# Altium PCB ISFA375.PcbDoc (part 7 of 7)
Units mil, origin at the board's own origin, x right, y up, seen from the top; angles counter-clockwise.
Board outline 5615 x 5520 mil, 6 copper layers (Top_SL, GND, POWER, Signal_Layer, GND2, Bottom_SL), stack 60.472 mil thick; 494 components, 307 nets, 1648 pads, 755 vias.
Unrouted connection lines stored in the file: 315.
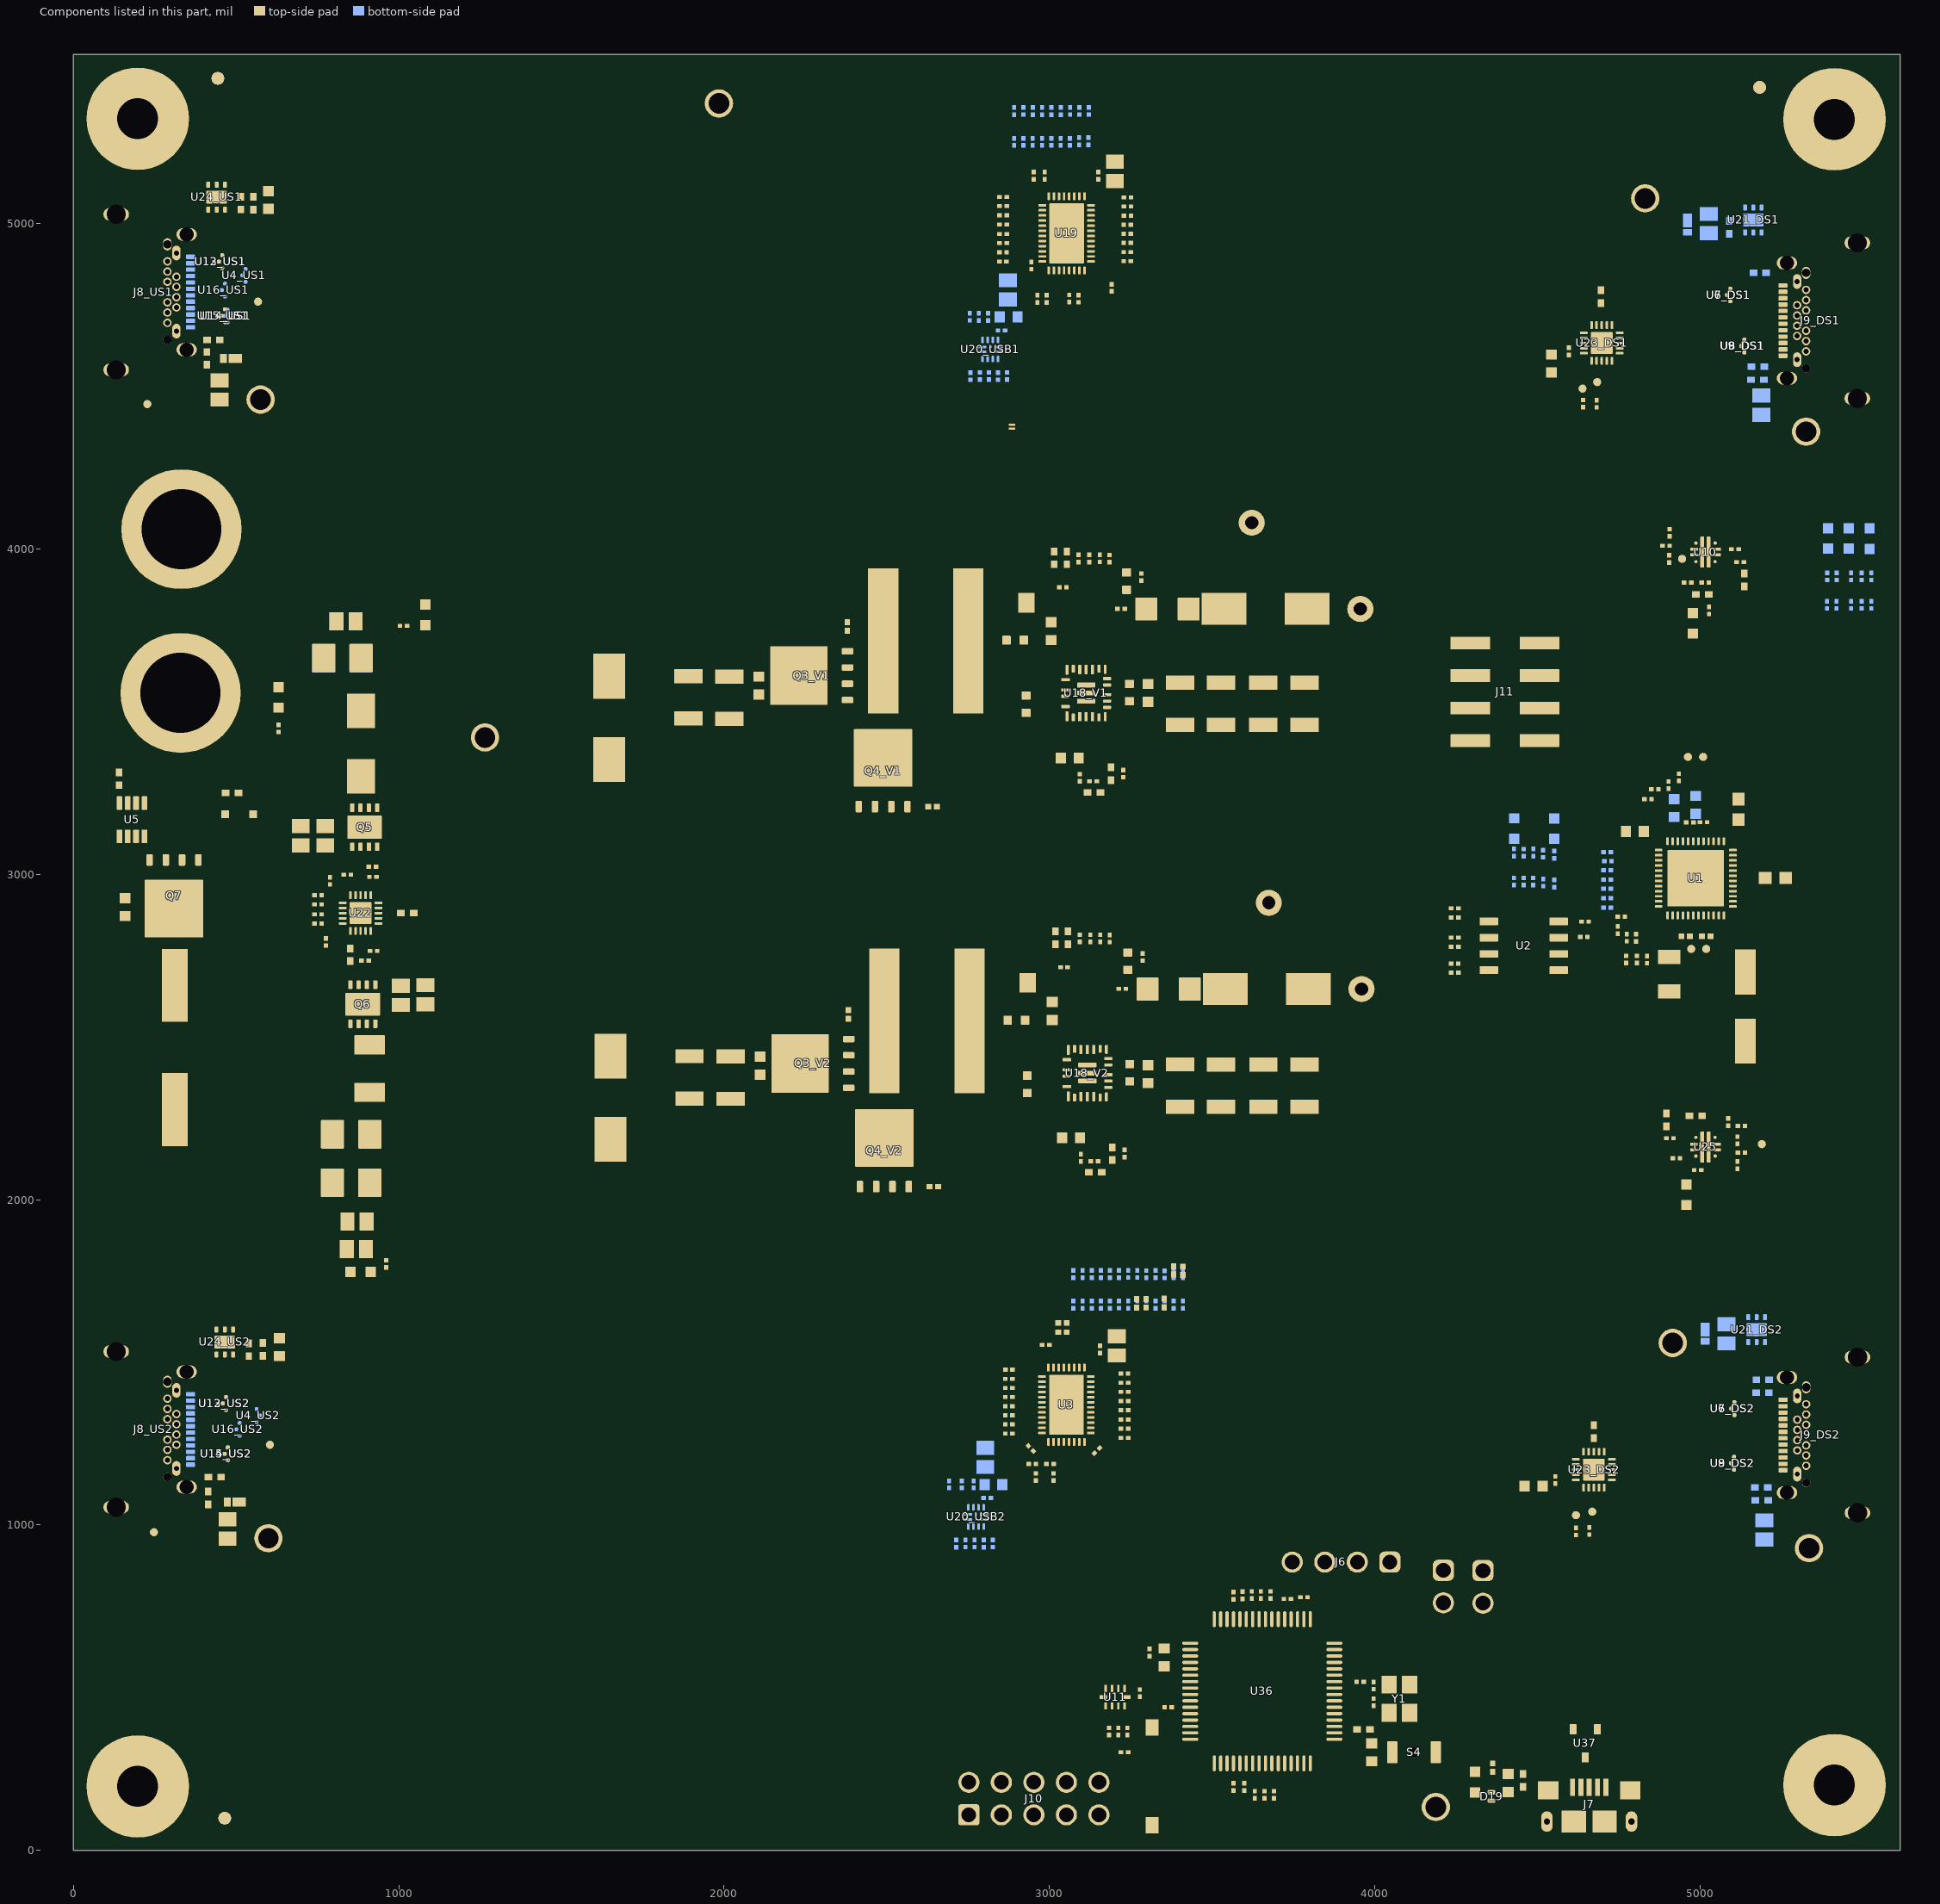
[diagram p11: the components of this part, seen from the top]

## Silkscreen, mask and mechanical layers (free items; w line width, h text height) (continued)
M10 Fab Notes:
  drawing of 189 lines, arcs and shapes, not listed
  text "DESIGN INFORMATION" at 12053.02,6356.17 h30
  text "MIN. TRACK WIDTH:" at 11408.46,6224.05 h30
  text "4.32" at 12504.7,6224.05 h30
  text "MIL" at 12659.46,6224.05 h30
  text "4mil" at 12474.71,6118 h30
  text "MIN. CLEARANCE:" at 11408.46,6099.92 h30
  text "MIL" at 12659.46,6099.92 h30
  text "MIN. VIA PAD SIZE:" at 11408.46,5975.8 h30
  text "4" at 12474.71,5975.8 h30
  text "MIL" at 12659.46,5975.8 h30
  text "0.1mm (4MIL)" at 12103.46,5845.9 h30
  text "MINIMUM ANNULAR RING" at 11079.23,5837.68 h30
  text "EXTERNAL" at 12811.46,5837.68 h30
  text "PER" at 11279.23,5727.55 h30
  text "IPC-D-275 CLASS 2 LEVEL C" at 11499.23,5727.54 h30
  text "MIL, HOLES" at 12987.46,5627.07 h30
  text "+/-" at 12595,5618.48 h30
  text "+/-" at 13449,5618.48 h30
  text "REGISTRATION TOLERANCES:" at 11079.23,5617.42 h30
  text "METAL" at 12279,5617.42 h30
  text "5" at 12855.2,5617.42 h30
  text "3" at 13688.2,5617.42 h30
  text "MIL" at 13804.46,5617.42 h30
  text "HOLE SIZE TOLERANCE (UNLESS OTHERWISE SPECIFIED):" at 11079.23,5519.1 h30
  text "+/-" at 13449,5516.23 h30
  text "3" at 13688.2,5515.17 h30
  text "MIL" at 13804.46,5515.17 h30
  text "MATERIAL:" at 11004.46,5377.52 h30
  text "FR-4 High Tg" at 11990.9,5249 h30
  text "X" at 11846.46,5241.01 h30
  text "FR-408" at 11425.46,5236.49 h30
  text "OTHER" at 12913.46,5236.49 h30
  text "62 MIL (1.6mm) +/-10%" at 11745.56,5093.46 h30
  text "X" at 11625.46,5091.01 h30
  text "THICKNESS:" at 11079.23,5085.24 h30
  text "OTHER" at 13030.46,5085.24 h30
  text "TOLERANCE:" at 11079.23,4946.92 h30
  text "X" at 11927.46,4946.92 h30
  text "ANSI IPC-6012 TYPE 3 CLASS 2" at 12105.48,4946.92 h30
  text "OTHER +/-" at 12105.46,4802.73 h30
  text "BOW & TWIST:" at 11079.23,4657.54 h30
  text "X" at 11927.46,4657.54 h30
  text "ANSI IPC-6012 TYPE 3 CLASS 2" at 12105.48,4657.54 h30
  text "OTHER +/-" at 12105.46,4510.85 h30
  text "DRILLING:" at 11004.46,4380.23 h30
  text "NC_DRILL FILES" at 12765.46,4275.04 h30
  text "REFERENCE:" at 11079.23,4271.1 h30
  text "X" at 11736.46,4271.01 h30
  text "AS SHOWN" at 11914.46,4271.1 h30
  text "X" at 12637.46,4271.1 h30
  text "OTHER" at 13063.46,4128.85 h30
  text "PTH COPPER THICKNESS:" at 11078.91,4125.32 h30
  text "X" at 12218.14,4125.32 h30
  text "20-30 um" at 12346.14,4125.32 h30
  text "BOARD FINISH:" at 11004.46,3977.73 h30
  text "SILKSCREEN:" at 11159.68,3867.6 h30
  text "X" at 12117.46,3867.6 h30
  text "TOP" at 12234.46,3867.6 h30
  text "X" at 12627.46,3867.6 h30
  text "BOTTOM" at 12745.46,3867.6 h30
  text "SILKSCREEN COLOR:" at 11159.68,3712.41 h30
  text "X" at 12116.46,3712.41 h30
  text "WHITE" at 12234.46,3712.41 h30
  text "OTHER" at 12745.46,3712.41 h30
  text "X" at 12247.46,3568.96 h30
  text "GREEN" at 12365.46,3568.96 h30
  text "OTHER" at 12983.46,3568.96 h30
  text "SOLDER RESIST COLOR:" at 11159.68,3562.1 h30
  text "X" at 12247.46,3414.71 h30
  text "MATTE" at 12365.46,3414.71 h30
  text "SEMI-GLOSS" at 12983,3414.07 h30
  text "IMMERSION GOLD (ENIG)" at 12065.46,3241.94 h30
  text "ENEPIG" at 13403,3234.72 h30
  text "SURFACE FINISH:" at 11004.46,3233.72 h30
  text "X" at 11887.46,3233.72 h30
  text "IMM. TIN/SILVER OR EQUIV" at 11334,3096.4 h30
  text "OTHER" at 12765.46,3092.47 h30
  text "ARRAY/PANEL:" at 11004.46,2937.09 h30
  text "CUT AND TRIM PER M1 BOARD OUTLINE" at 12065.46,2928.87 h30
  text "N.C. ROUTE" at 12065.46,2792.9 h30
  text "X" at 12753.46,2792.9 h30
  text "V. SCORE" at 12931.46,2792.9 h30
  text "CERTIFICATION:" at 11004.46,2663.77 h30
  text "MATERIALS AND WORKMANSHIP FOR ALL PCBS" at 11729.46,2663.77 h30
  text "TO MEET OR EXCEED THE REQUIREMENTS OF:" at 11729.46,2569.71 h30
  text "X" at 11366.97,2441.08 h30
  text "ANSI IPC-A-600F CLASS ->" at 11494.96,2441.08 h30
  text "X" at 13142.97,2441.08 h30
  text "2" at 13252.96,2441.08 h30
  text "1" at 12937.96,2439.58 h30
  text "3" at 13606.96,2439.58 h30
  text "X" at 12178.97,2293.39 h30
  text "RoHS" at 12306.96,2293.39 h30
  text "OTHER" at 12951.36,2293.39 h30
  text "PER ORDER" at 13348.42,2293.39 h30
  text "ALL BOARDS MUST MEET OR EXCEED UL94-V0 REQUIREMENTS." at 11032,2139.57 h30
  text "PCB MUST BEAR THE UL94V-0 UL REGISTERED MATERIAL ID NUMBER" at 11032,2023.5 h30
  text "ADDITIONAL REQUIREMENTS:" at 11004.46,1854.08 h30
  text "MICROSECTION:" at 11079.23,1746.95 h30
  text "YES" at 11984.96,1746.95 h30
  text "REQUIRED" at 12846.46,1602.62 h30
  text "BARE BOARD ELEC. TEST:" at 11079.23,1599.76 h30
  text "NONE" at 12384.96,1599.76 h30
  text "X" at 12728.46,1599.76 h30
  text "PER ORDER" at 13438.46,1599.76 h30
  text "XX MIL VIAS REQUIRE NON-CONDUCTIVE FILL AND PLANARIZE" at 10683,1394 h30
  text "XX MIL VIAS REQUIRE CONDUCTIVE FILL AND PLANARIZE" at 11255.38,1290.84 h30
  text "X" at 11141.97,1139.39 h30
  text "LAYER 4 (INNER LAYER) 4.32 MIL WIDE,  / TRACES REQUIRE 90 OHM DIFFERENTIAL IMPEDANCE" at 11246.39,1116.41 h30
  text "X" at 11149.97,973.39 h30
  text "LAYER 1 & 6 (OUTER LAYERS) 6.5 MIL WIDE,  / TRACES REQUIRE 90 OHM DIFFERENTIAL IMPEDANCE" at 10624,898 h30
  text ".Layer_Name" at 248,-858.49 h30
M11 Gerber Information:
  lines w10: -621,-930.17 5979,-930.17 ; -621,-726.83 5981,-726.83 ; -621,-523.5 -621,-1133.5 3384,-1133.5 5981,-1133.5 5981,-523.5 -620.5,-523.5 -620.5,-1133.5 955,-1133.5 ; 1844,-1133.5 1844,-523.5 ; 3111,-726.83 3111,-523.5 ; 3951,-726.83 3951,-523.5 ; 4573,-1140 4573,-937.17
  text "ALL ARTWORK VIEWED FROM TOP SIDE" at -557.5,-655.67 h30
  text "BOARD #:" at 1919,-655.67 h30
  text ".PRJ_Number" at 2464.5,-655.67 h30
  text "REV:" at 3309,-655.67 h30
  text ".PCB_Rev" at 3600.5,-655.67 h30
  text "SVN REV:" at 4147,-655.67 h30
  text ".VersionControl_RevNumber" at 4653,-655.67 h30
  text "LAYER NAME =" at -557.5,-858.49 h30
  text "TID #:" at 1919,-859 h30
  text ".TID" at 2464.5,-859 h30
  text "PLOT NAME =" at -557.5,-1064.34 h30
  text ".plot_File_Name" at 248,-1064.34 h30
  text "GENERATED    :" at 1921,-1064.34 h30
  text ".Print_Date" at 2790.5,-1064.34 h30
  text ".Print_Time" at 3519.5,-1064.34 h30
  text "TEXAS INSTRUMENTS" at 4784,-1064.34 h30
M12 Stackup:
  drawing of 399 lines, arcs and shapes, not listed
  text "Layer" at 6938.2,2460 h30
  text "Name" at 7153.15,2460 h30
  text "Material" at 7628.02,2460 h30
  text "Thickness" at 8067.91,2460 h30
  text "Constant" at 8402.83,2460 h30
  text "Board Layer Stack" at 8697.76,2460 h30
  text "Top Overlay" at 7153.15,2400 h30
  text "Top Solder" at 7153.15,2340 h30
  text "Solder Resist" at 7628.02,2340 h30
  text "0.40mil" at 8067.91,2340 h30
  text "3.5" at 8402.83,2340 h30
  text "1" at 6938.2,2280 h30
  text "Top_SL" at 7153.15,2280 h30
  text "1.38mil" at 8067.91,2280 h30
  text "Dielectric 1" at 7153.15,2220 h30
  text "FR-4" at 7628.02,2220 h30
  text "5.67mil" at 8067.91,2220 h30
  text "4.2" at 8402.83,2220 h30
  text "2" at 6938.2,2160 h30
  text "GND" at 7153.15,2160 h30
  text "1.38mil" at 8067.91,2160 h30
  text "Dielectric 2" at 7153.15,2100 h30
  text "FR-4" at 7628.02,2100 h30
  text "16.93mil" at 8067.91,2100 h30
  text "4.2" at 8402.83,2100 h30
  text "3" at 6938.2,2040 h30
  text "POWER" at 7153.15,2040 h30
  text "1.38mil" at 8067.91,2040 h30
  text "Dielectric 3" at 7153.15,1980 h30
  text "FR-4" at 7628.02,1980 h30
  text "7.01mil" at 8067.91,1980 h30
  text "4.2" at 8402.83,1980 h30
  text "4" at 6938.2,1920 h30
  text "Signal_Layer" at 7153.15,1920 h30
  text "1.38mil" at 8067.91,1920 h30
  text "Dielectric 4" at 7153.15,1860 h30
  text "FR-4" at 7628.02,1860 h30
  text "16.93mil" at 8067.91,1860 h30
  text "4.2" at 8402.83,1860 h30
  text "5" at 6938.2,1800 h30
  text "GND2" at 7153.15,1800 h30
  text "1.38mil" at 8067.91,1800 h30
  text "Dielectric 5" at 7153.15,1740 h30
  text "FR-4" at 7628.02,1740 h30
  text "5.67mil" at 8067.91,1740 h30
  text "4.2" at 8402.83,1740 h30
  text "6" at 6938.2,1680 h30
  text "Bottom_SL" at 7153.15,1680 h30
  text "1.38mil" at 8067.91,1680 h30
  text "Bottom Solder" at 7153.15,1620 h30
  text "Solder Resist" at 7628.02,1620 h30
  text "0.40mil" at 8067.91,1620 h30
  text "3.5" at 8402.83,1620 h30
  text "Bottom Overlay" at 7153.15,1560 h30
  text ".Layer_Name" at 248,-858.49 h30
M13 Component Bodies Top:
  text ".Layer_Name" at 248,-858.49 h30
M14 Component Bodies Bottom:
  text ".Layer_Name" at 248,-858.49 h30
M15 Courtyards Top:
  text ".Layer_Name" at 248,-858.49 h30
M16 Courtyards Bottom:
  text ".Layer_Name" at 248,-858.49 h30
Drill Drawing:
  drawing of 184 lines, arcs and shapes, not listed
  text "Symbol" at 7600.23,7570.57 h36
  text "Quantity" at 7750.44,7570.57 h36
  text "Finished Hole Size" at 7916.38,7570.57 h36
  text "Plated" at 8234.59,7570.57 h36
  text "Hole Type" at 8364.09,7570.57 h36
  text "Drill Layer Pair" at 8551.61,7570.57 h36
  text "Hole Tolerance" at 8852.37,7570.57 h36
  text "4" at 7750.44,7508.52 h30
  text "25.59mil (0.650mm)" at 7916.38,7508.52 h30
  text "NPTH" at 8234.59,7508.52 h30
  text "Round" at 8364.09,7508.52 h30
  text "Top_SL - Bottom_SL" at 8551.61,7508.52 h30
  text "1" at 7750.44,7446.47 h30
  text "29.53mil (0.750mm)" at 7916.38,7446.47 h30
  text "NPTH" at 8234.59,7446.47 h30
  text "Round" at 8364.09,7446.47 h30
  text "Top_SL - Bottom_SL" at 8551.61,7446.47 h30
  text "16" at 7750.44,7384.42 h30
  text "6.00mil (0.152mm)" at 7916.38,7384.42 h30
  text "PTH" at 8234.59,7384.42 h30
  text "Round" at 8364.09,7384.42 h30
  text "Top_SL - Bottom_SL" at 8551.61,7384.42 h30
  text "66" at 7750.44,7322.37 h30
  text "7.87mil (0.200mm)" at 7916.38,7322.37 h30
  text "PTH" at 8234.59,7322.37 h30
  text "Round" at 8364.09,7322.37 h30
  text "Top_SL - Bottom_SL" at 8551.61,7322.37 h30
  text "C" at 7584.16,7312.38 h27.58
  text "651" at 7750.44,7260.33 h30
  text "8.00mil (0.203mm)" at 7916.38,7260.33 h30
  text "PTH" at 8234.59,7260.33 h30
  text "Round" at 8364.09,7260.33 h30
  text "Top_SL - Bottom_SL" at 8551.61,7260.33 h30
  text "40" at 7750.44,7198.28 h30
  text "15.75mil (0.400mm)" at 7916.38,7198.28 h30
  text "PTH" at 8234.59,7198.28 h30
  text "Round" at 8364.09,7198.28 h30
  text "Top_SL - Bottom_SL" at 8551.61,7198.28 h30
  text "6" at 7750.44,7136.23 h30
  text "16.00mil (0.406mm)" at 7916.38,7136.23 h30
  text "PTH" at 8234.59,7136.23 h30
  text "Round" at 8364.09,7136.23 h30
  text "Top_SL - Bottom_SL" at 8551.61,7136.23 h30
  text "8" at 7750.44,7074.18 h30
  text "28.00mil (0.711mm)" at 7916.38,7074.18 h30
  text "PTH" at 8234.59,7074.18 h30
  text "Round" at 8364.09,7074.18 h30
  text "Top_SL - Bottom_SL" at 8551.61,7074.18 h30
  text "4" at 7750.44,7012.13 h30
  text "40.00mil (1.016mm)" at 7916.38,7012.13 h30
  text "PTH" at 8234.59,7012.13 h30
  text "Round" at 8364.09,7012.13 h30
  text "Top_SL - Bottom_SL" at 8551.61,7012.13 h30
  text "18" at 7750.44,6950.09 h30
  text "45.28mil (1.150mm)" at 7916.38,6950.09 h30
  text "PTH" at 8234.59,6950.09 h30
  text "Round" at 8364.09,6950.09 h30
  text "Top_SL - Bottom_SL" at 8551.61,6950.09 h30
  text "9" at 7750.44,6888.04 h30
  text "63.00mil (1.600mm)" at 7916.38,6888.04 h30
  text "PTH" at 8234.59,6888.04 h30
  text "Round" at 8364.09,6888.04 h30
  text "Top_SL - Bottom_SL" at 8551.61,6888.04 h30
  text "12" at 7750.44,6825.99 h30
  text "125.98mil (3.200mm)" at 7916.38,6825.99 h30
  text "PTH" at 8234.59,6825.99 h30
  text "Round" at 8364.09,6825.99 h30
  text "Top_SL - Bottom_SL" at 8551.61,6825.99 h30
  text "D" at 7584.16,6816 h27.58
  text "2" at 7750.44,6763.94 h30
  text "246.06mil (6.250mm)" at 7916.38,6763.94 h30
  text "PTH" at 8234.59,6763.94 h30
  text "Round" at 8364.09,6763.94 h30
  text "Top_SL - Bottom_SL" at 8551.61,6763.94 h30
  text "4" at 7750.44,6701.89 h30
  text "25.59mil (0.650mm)" at 7916.38,6701.89 h30
  text "NPTH" at 8234.59,6701.89 h30
  text "Slot" at 8364.09,6701.89 h30
  text "Top_SL - Bottom_SL" at 8551.61,6701.89 h30
  text "8" at 7750.44,6639.85 h30
  text "15.75mil (0.400mm)" at 7916.38,6639.85 h30
  text "PTH" at 8234.59,6639.85 h30
  text "Slot" at 8364.09,6639.85 h30
  text "Top_SL - Bottom_SL" at 8551.61,6639.85 h30
  text "2" at 7750.44,6577.8 h30
  text "19.69mil (0.500mm)" at 7916.38,6577.8 h30
  text "PTH" at 8234.59,6577.8 h30
  text "Slot" at 8364.09,6577.8 h30
  text "Top_SL - Bottom_SL" at 8551.61,6577.8 h30
  text "A" at 7584.16,6567.8 h27.58
  text "8" at 7750.44,6515.75 h30
  text "43.31mil (1.100mm)" at 7916.38,6515.75 h30
  text "PTH" at 8234.59,6515.75 h30
  text "Slot" at 8364.09,6515.75 h30
  text "Top_SL - Bottom_SL" at 8551.61,6515.75 h30
  text "8" at 7750.44,6453.7 h30
  text "59.06mil (1.500mm)" at 7916.38,6453.7 h30
  text "PTH" at 8234.59,6453.7 h30
  text "Slot" at 8364.09,6453.7 h30
  text "Top_SL - Bottom_SL" at 8551.61,6453.7 h30
  text "867 Total" at 7750.44,6391.65 h30
  text "Slot definitions :" at 7600.23,6348.22 h30
  text "Routed Path Length" at 7825.18,6348.22 h30
  text "= Calculated from tool start centre position to tool end centre position." at 8094.56,6348.22 h30
  text "Hole Length" at 7825.18,6323.4 h30
  text "= Routed Path Length + Tool Size = Slot length as defined in the PCB layout" at 7994.84,6323.4 h30
  text ".Layer_Name" at 248,-858.49 h30
M17 Embedded Cavity:
  text ".Layer_Name" at 248,-858.49 h30
M18 Embedded Assembly:
  text ".Layer_Name" at 248,-858.49 h30
M19 Embedded Keepout:
  text ".Layer_Name" at 248,-858.49 h30

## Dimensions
-329,-400 to 671,-400 on M2 Board Dimensions
-329,0 to 0,5520 on M2 Board Dimensions
0,0 to 5615,0 on M2 Board Dimensions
